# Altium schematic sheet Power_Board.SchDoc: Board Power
size A4; Date: Not used; ApprovedBy: Not used; CheckedBy: Not used; Author: Not used; CompanyName: STMicroelectronics; DrawnBy: Not used; Engineer: Not used; Organization: Not used; Address1: Not used; Address2: Not used; Address3: Not used; Address4: Not used; DocumentNumber: Not used; Revision: Not used; SheetNumber: 20; SheetTotal: 23
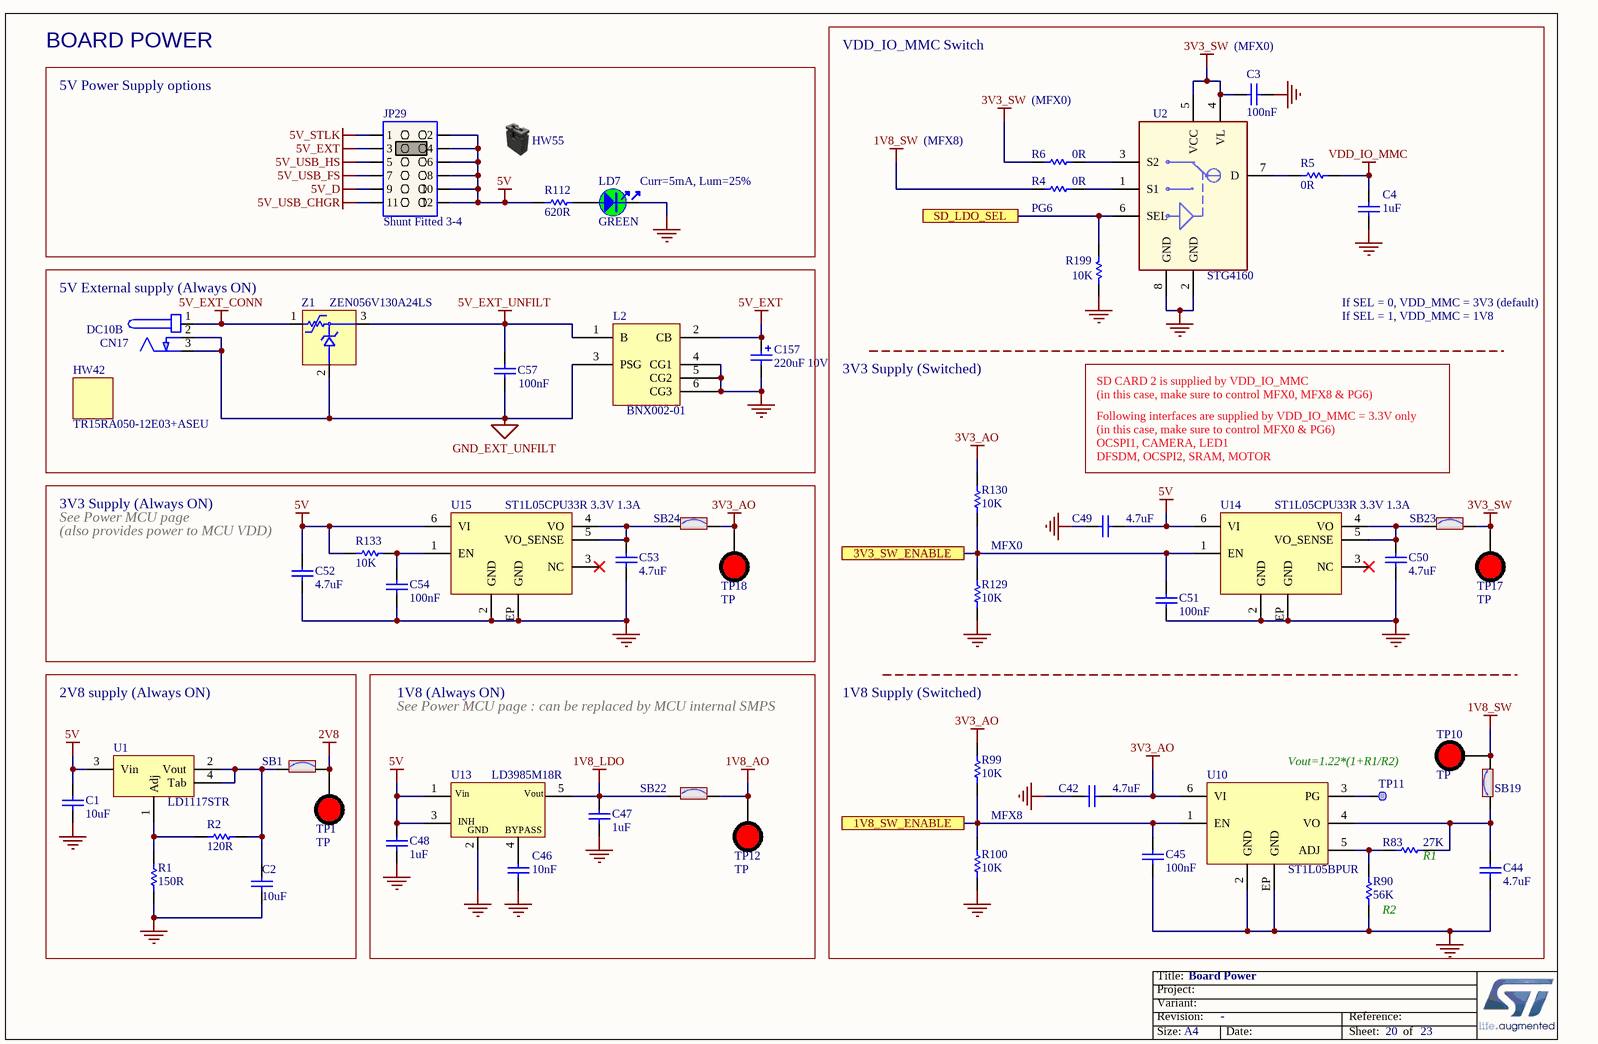
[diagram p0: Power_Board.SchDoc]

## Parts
C1  value 10uF  [C0603]  (hidden comment: Capacitor)
C2  value 10uF  [C0603]  (hidden comment: Capacitor)
C3  value 100nF  [C0402]  (hidden comment: Capacitor)
C4  value 1uF  [C0603]  (hidden comment: Capacitor)
C42  value 4.7uF  [C0603]  (hidden comment: Capacitor)
C44  value 4.7uF  [C0603]  (hidden comment: Capacitor)
C45  value 100nF  [C0402]  (hidden comment: Capacitor)
C46  value 10nF  [C0402]  (hidden comment: Capacitor)
C47  value 1uF  [C0402]  (hidden comment: Capacitor)
C48  value 1uF  [C0402]  (hidden comment: Capacitor)
C49  value 4.7uF  [C0603]  (hidden comment: Capacitor)
C50  value 4.7uF  [C0603]  (hidden comment: Capacitor)
C51  value 100nF  [C0402]  (hidden comment: Capacitor)
C52  value 4.7uF  [C0603]  (hidden comment: Capacitor)
C53  value 4.7uF  [C0603]  (hidden comment: Capacitor)
C54  value 100nF  [C0402]  (hidden comment: Capacitor)
C57  value 100nF  [C0402]  (hidden comment: Capacitor)
C157  value 220uF 10V  [CPOL_TAJ-C_2312_H2P6]  (hidden comment: Cap_POL_TANA)
CN17  value DC10B  [CON_DC-POWER-SOCKET_CLIFF_FC68149_DC10B]  (hidden comment: Power_Jack_DC10B)
HW42  value TR15RA050-12E03+ASEU  (hidden comment: Hardware)  (mechanical)
HW55  Shunt Black 2.54mm  (value not drawn)  (mechanical)
JP29  value Shunt Fitted 3-4  [CON_SAMTEC_TSW-106-07-X-D]  (hidden comment: Jumper_Header 6x2 Fitted 3-4)
L2  BNX002-01  [FIL_MURATA_BNX002-01]
LD7  value GREEN  [LED_0603_OSRAM_LG-Q396-PS-35_GREEN_1A2K_H0P4]  (hidden comment: LED_green)
R1  value 150R  [R0603]  (hidden comment: Resistor)
R2  value 120R  [R0603]  (hidden comment: Resistor)
R4  value 0R  [R0603]  (hidden comment: Resistor)
R5  value 0R  [R0603]  (hidden comment: Resistor)
R6  value 0R  [R0603]  (hidden comment: Resistor)
R83  value 27K  [R0402]  (hidden comment: Resistor)
R90  value 56K  [R0402]  (hidden comment: Resistor)
R99  value 10K  [R0402]  (hidden comment: Resistor)
R100  value 10K  [R0402]  (hidden comment: Resistor)
R112  value 620R  [R0402]  (hidden comment: Resistor)
R129  value 10K  [R0402]  (hidden comment: Resistor)
R130  value 10K  [R0402]  (hidden comment: Resistor)
R133  value 10K  [R0402]  (hidden comment: Resistor)
R199  value 10K  [R0402]  (hidden comment: Resistor)
SB1  SB_ON  [SOLDER-BRIDGE_R0603-0R]  (value not drawn)
SB19  SB_ON  [SOLDER-BRIDGE_R0603-0R]  (value not drawn)
SB22  SB_ON  [SOLDER-BRIDGE_R0603-0R]  (value not drawn)
SB23  SB_ON  [SOLDER-BRIDGE_R0603-0R]  (value not drawn)
SB24  SB_ON  [SOLDER-BRIDGE_R0603-0R]  (value not drawn)
TP1  value TP  [TP_PTH-1MM_TEST-TERMINAL_RS_262-2185_RED]  (hidden comment: Test_pin_conn_red)
TP10  value TP  [TP_PTH-1MM_TEST-TERMINAL_RS_262-2185_RED]  (hidden comment: Test_pin_conn_red)
TP11  Test Point  [TP_SMD_1MM]  (value not drawn)  (no BOM)
TP12  value TP  [TP_PTH-1MM_TEST-TERMINAL_RS_262-2185_RED]  (hidden comment: Test_pin_conn_red)
TP17  value TP  [TP_PTH-1MM_TEST-TERMINAL_RS_262-2185_RED]  (hidden comment: Test_pin_conn_red)
TP18  value TP  [TP_PTH-1MM_TEST-TERMINAL_RS_262-2185_RED]  (hidden comment: Test_pin_conn_red)
U1  LD1117STR  [REG_SOT223-TAB]
U2  STG4160  [ESD_FLIP-CHIP-BGA8_1P9X0P9_P050]
U10  ST1L05BPUR  [ICC_DFN6-EPAD_3X3_P095]
U13  LD3985M18R  [REG_SOT23-5L]
U14  value ST1L05CPU33R 3.3V 1.3A  [ICC_DFN6-EPAD_3X3_P095]  (hidden comment: ST1L05CPU33R)
U15  value ST1L05CPU33R 3.3V 1.3A  [ICC_DFN6-EPAD_3X3_P095]  (hidden comment: ST1L05CPU33R)
Z1  ZEN056V130A24LS  [DIOZ_LITTELFUSE_ZEN056V130A24LS]

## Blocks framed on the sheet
BOARD POWER: HW55 JP29 LD7 R112
5V External supply (Always ON): C57 C157 CN17 HW42 L2 Z1
2V8 supply (Always ON): C1 C2 R1 R2 SB1 TP1 U1

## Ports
1V8_SW_ENABLE, 3V3_SW_ENABLE, SD_LDO_SEL

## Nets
1V8_AO: SB22.2 TP12.1
1V8_LDO: C47.2 SB22.1 U13.5(Vout)
1V8_SW: R4.1 SB19.2 TP10.1
2V8: SB1.2 TP1.1
3V3_AO: C42.1 R99.1 R130.1 SB24.2 TP18.1 U10.6(VI)
3V3_SW: C3.1 R6.1 SB23.2 TP17.1 U2.4(VL) U2.5(VCC)
5V: C1.2 C48.2 C49.1 C52.2 JP29.2 JP29.4 JP29.6 JP29.8 JP29.10 JP29.12 R112.1 R133.2 U1.3(Vin) U13.1(Vin) U13.3(CE) U14.6(VI) U15.6(VI)
5V_D: JP29.9
5V_EXT: C157.1 JP29.3 L2.2(CB)
5V_EXT_CONN: CN17.1 Z1.1
5V_EXT_UNFILT: C57.1 L2.1(B) Z1.3
5V_STLK: JP29.1
5V_USB_CHGR: JP29.11
5V_USB_FS: JP29.7
5V_USB_HS: JP29.5
GND: C1.1 C2.1 C3.2 C4.1 C42.2 C44.1 C45.2 C46.1 C47.1 C48.1 C49.2 C50.1 C51.2 C52.1 C53.1 C54.2 C157.2 L2.4(CG1) L2.5(CG2) L2.6(CG3) LD7.2 R1.1 R90.1 R100.2 R129.2 R199.1 U2.2(GND) U2.8(GND) U10.2(GND) U10.EP(GND) U13.2(GND) U14.2(GND) U14.EP(GND) U15.2(GND) U15.EP(GND)
GND_EXT_UNFILT: C57.2 CN17.2 CN17.3 L2.3(PSG) Z1.2
VDD_IO_MMC: C4.2 R5.2
1V8_SW_ENABLE: C45.1 R99.2 R100.1 U10.1(EN) ; port 1V8_SW_ENABLE
3V3_SW_ENABLE: C51.1 R129.1 R130.2 U14.1(EN) ; port 3V3_SW_ENABLE
SD_LDO_SEL: R199.2 U2.6(SEL) ; port SD_LDO_SEL
NetC2_2: C2.2 R2.1 SB1.1 U1.2(Vout) U1.4(Tab)
NetC44_2: C44.2 R83.1 SB19.1 U10.4(VO)
NetC46_2: C46.2 U13.4(BYPASS)
NetC50_2: C50.2 SB23.1 U14.4(VO) U14.5(VO_SENSE)
NetC53_2: C53.2 SB24.1 U15.4(VO) U15.5(VO_SENSE)
NetC54_1: C54.1 R133.1 U15.1(EN)
NetLD7_1: LD7.1 R112.2
NetR1_2: R1.2 R2.2 U1.1(Adj)
NetR4_2: R4.2 U2.1(S1)
NetR5_1: R5.1 U2.7(D)
NetR6_2: R6.2 U2.3(S2)
NetR83_2: R83.2 R90.2 U10.5(ADJ)
NetTP11_1: TP11.1 U10.3(PG)

Not connected (* = marked no-connect by the designer): U14 3(NC)*; U15 3(NC)*

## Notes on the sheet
- VDD_IO_MMC Switch
- (near C3) (MFX0)
- 5V Power Supply options
- (MFX0)
- (near LD7) Curr=5mA, Lum=25%
- (MFX8)
- (near R4) PG6
- If SEL = 0, VDD_MMC = 3V3 (default)
- If SEL = 1, VDD_MMC = 1V8
- 3V3 Supply (Switched)
- SD CARD 2 is supplied by VDD_IO_MMC
  (in this case, make sure to control MFX0, MFX8 & PG6)
- 3V3 Supply (Always ON)
- See Power MCU page
- Following interfaces are supplied by VDD_IO_MMC = 3.3V only
  (in this case, make sure to control MFX0 & PG6)
  OCSPI1, CAMERA, LED1
  DFSDM, OCSPI2, SRAM, MOTOR
- (near C52) (also provides power to MCU VDD)
- MFX0
- 1V8 (Always ON)
- See Power MCU page : can be replaced by MCU internal SMPS
- 1V8 Supply (Switched)
- Vout=1.22*(1+R1/R2)
- MFX8
- (near R83) R1
- (near R90) R2

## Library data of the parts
C1 C2 = MCD-00243: Capacitor, MLCC, 10uF, 6V3, X5R, 10%, 0603, T=0,8mm; Manufacturer_Part_Number: CC0603KRX5R5BB106; Manufacturer: YAGEO; Provided_By: SUBCO; ECCN_US: EAR99; ECCN_EU: NEC
C3 C45 C51 C54 C57 = MCD-00006: Capacitor, MLCC, 100nF, 16V, X7R, 10%, 0402, T=0.5mm; Manufacturer_Part_Number: CC0402KRX7R7BB104; Manufacturer: YAGEO; Alternate_Manufacturer_Part_Number: GCM155R71C104KA55D; Alternate_Manufacturer: MURATA; Provided_By: SUBCO; ECCN_US: EAR99; ECCN_EU: NEC
C4 = MCD-00010: Capacitor, MLCC, 1uF, 16V, X5R, 10%, 0603, T=0,8mm; Manufacturer_Part_Number: CC0603KRX5R7BB105; Manufacturer: YAGEO; Provided_By: SUBCO; ECCN_US: EAR99; ECCN_EU: NEC
C42 C44 C50 C53 = MCD-01121: Capacitor, MLCC, 4.7uF, 10V, X5R, 20%, 0603, T=0,8mm; Manufacturer_Part_Number: GRM188R61A475ME15; Manufacturer: MURATA; Provided_By: SUBCO; ECCN_US: EAR99; ECCN_EU: NEC
C46 = MCD-00011: Capacitor, MLCC, 10nF, 16V, X7R, 10%, 0402, T=0.5mm; Manufacturer_Part_Number: CC0402KRX7R7BB103; Manufacturer: YAGEO; Provided_By: SUBCO; ECCN_US: EAR99; ECCN_EU: NEC
C47 C48 = MCD-00095: Capacitor, MLCC, 1uF, 6V3, X5R, 10%, 0402, T=0,5mm; Manufacturer_Part_Number: GRM155R61E105KA12; Manufacturer: MURATA; Alternate_Manufacturer_Part_Number: GRM155R60J105KE19; Provided_By: SUBCO; ECCN_US: EAR99; ECCN_EU: NEC
C49 C52 = MCD-00097: Capacitor, MLCC, 4.7uF, 16V, X5R, 20%, 0603, T=0,8mm; Manufacturer_Part_Number: GRM188R61C475KE11; Manufacturer: MURATA; Alternate_Manufacturer_Part_Number: GRM188R61C475MAAJ; Provided_By: SUBCO; ECCN_US: EAR99; ECCN_EU: NEC
C157 = MCD-00142: Capacitor, Tantalum, 220uF, 10V, 10%, 500mOhms, pkg Type_C (6032 metric), T=2.6mm; Manufacturer_Part_Number: TAJC227K010R; Manufacturer: AVX; Provided_By: SUBCO; ECCN_US: EAR99; ECCN_EU: NEC
CN17 = MCD-00173: DC-Power-Jack, 2.5mm, 5A, RA, TH; Manufacturer: CLIFF; Part_Type: Connector; BMS_Part_Number: 9087803; Provided_By: SUBCO
HW42 = MCD-01420: External CA Wall power supply 5V 2A Switching Adapter, Level VI, Wallmount, 15W, 90-264VAC Input, 5VDC Output, 5.5x2.5x12mm Straight, Grey Case, DC Cable 1800mm; Part_Type: Mechanical; Manufacturer: CINCON; BMS_Part_Number: 9027030; Provided_By: ST
HW55 = MCD-00043: SHUNT 2.54mm BLACK; Part_Type: Mechanical; Manufacturer: SAMTEC; Alternate_Manufacturer_Part_Number: 316102S111A; Alternate_Manufacturer: JIUBABA; Value: SNT-100-BK-G; Provided_By: SUBCO
JP29 = MCD-01147: Header, 6x2, 2,54mm, VR, TH, Height 5.84mm/2.54mm - Shunt Fitted 1-2; Part_Type: Connector; Manufacturer_Part_Number: TSW-106-07-x-D; Manufacturer: SAMTEC; Provided_By: SUBCO
L2 = MCD-00150: Through HOLE DC power EMI line filter, 40dB min (1MHz - 1GHz) insertion loss; Manufacturer: MURATA; Part_Type: Inductor; BMS_Part_Number: 9049203; Provided_By: SUBCO; ECCN_US: EAR99; ECCN_EU: NEC
LD7 = MCD-00588: LED Green, 0603 SMD, Forward Voltage Typ=2V, Max=2.5V; Part_Type: Display; Manufacturer_Part_Number: LG Q396-PS-35; Manufacturer: OSRAM OPTO SEMICONDUCTORS; Alternate_Manufacturer_Part_Number: VLMTG1300-GS08; Alternate_Manufacturer: VISHAY SEMICONDUCTOR OPTO DIVISION; Provided_By: SUBCO
R1 = MCD-00394: Resistor,150,0603,1%,1/10W; Manufacturer_Part_Number: RC0603FR-07150RL; Manufacturer: YAGEO; Provided_By: SUBCO; ECCN_US: EAR99; ECCN_EU: NEC
R2 = MCD-00338: Resistor,120R,0603,1%,1/10W; Manufacturer_Part_Number: RC0603FR-07120RL; Manufacturer: YAGEO; BMS_Part_Number: 9129734; Provided_By: SUBCO; ECCN_US: EAR99; ECCN_EU: NEC
R4-R6 = MCD-00056: Resistor,0R,0603,5%,1/10W; Manufacturer_Part_Number: RC0603JR-070RL; Manufacturer: YAGEO; Provided_By: SUBCO; ECCN_US: EAR99; ECCN_EU: NEC
R83 = MCD-00443: Resistor,27K,0402,1%,1/16W; Manufacturer_Part_Number: RC0402FR-0727KL; Manufacturer: YAGEO; Provided_By: SUBCO; ECCN_US: EAR99; ECCN_EU: NEC
R90 = MCD-00493: Resistor,56K,0402,1%,1/16W; Manufacturer_Part_Number: RC0402FR-0756KL; Manufacturer: YAGEO; Provided_By: SUBCO; ECCN_US: EAR99; ECCN_EU: NEC
R99 R100 R129 R130 R133 R199 = MCD-00053: Resistor,10K,0402,1%,1/16W; Manufacturer_Part_Number: RC0402FR-0710KL; Manufacturer: YAGEO; Provided_By: SUBCO; ECCN_US: EAR99; ECCN_EU: NEC
R112 = MCD-00499: Resistor,620R,0402,1%,1/16W; Manufacturer_Part_Number: RC0402FR-07620RL; Manufacturer: YAGEO; Provided_By: SUBCO; ECCN_US: EAR99; ECCN_EU: NEC
SB1 SB19 SB22-SB24 = MCD-00071: Solder Bridge ON; Part_Type: Mechanical; Manufacturer_Part_Number: RC0603JR-070RL; Manufacturer: YAGEO; Provided_By: SUBCO
TP1 TP10 TP12 TP17 TP18 = MCD-00712: RS Pro 1mm Red Test Terminal; Part_Type: Mechanical; Manufacturer_Part_Number: 262-2185; Provided_By: SUBCO
TP11 = MCD-00074: Test Point 1mm; Part_Type: Mechanical
U1 = MCD-00721: LDO Voltage Regulator, Adjustable, 15V in, 1.1V drop, 1.25V to 15V/0.8A out, SOT-223-3; Part_Type: IC; Manufacturer: STMICROELECTRONICS; BMS_Part_Number: 9176132; Provided_By: SUBCO with ST control; ECCN_US: EAR99; ECCN_EU: NEC
U2 = MCD-00668: Low voltage 0.5 ohm single SPDT switch with break-before-make feature and 15 kV contact ESD protection; Manufacturer_Part_Number: STG4160BJR; Manufacturer: STMICROELECTRONICS; Part_Type: IC; Provided_By: SUBCO with ST control; ECCN_US: EAR99; ECCN_EU: NEC
U10 = MCD-00581: LDO Linear Voltage Regulator IC Positive Adjustable 1 Output Adjustable 1.3A 6-DFN (3x3); Manufacturer: STMICROELECTRONICS; BMS_Part_Number: 9176239; Provided_By: SUBCO with ST control; ECCN_US: EAR99; ECCN_EU: NEC
U13 = MCD-00078: Ultra low drop-low noise BiCMOS voltage, regulators low ESR capacitors compatible; Manufacturer: STMICROELECTRONICS; Part_Type: IC; BMS_Part_Number: 9176159; Provided_By: SUBCO with ST control; ECCN_US: EAR99; ECCN_EU: NEC
U14 U15 = MCD-01025: LDO, 3.3V, 1.3A, Very low quiescent current BiCMOS voltage regulator; Part_Type: IC; Manufacturer: STMICROELECTRONICS; BMS_Part_Number: 9176246; Provided_By: SUBCO with ST control; ECCN_US: EAR99; ECCN_EU: NEC
Z1 = MCD-00149: Protection circuit Zener Diode; Manufacturer: LITTLEFUSE; BMS_Part_Number: 9127091; Provided_By: SUBCO; ECCN_US: EAR99; ECCN_EU: NEC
